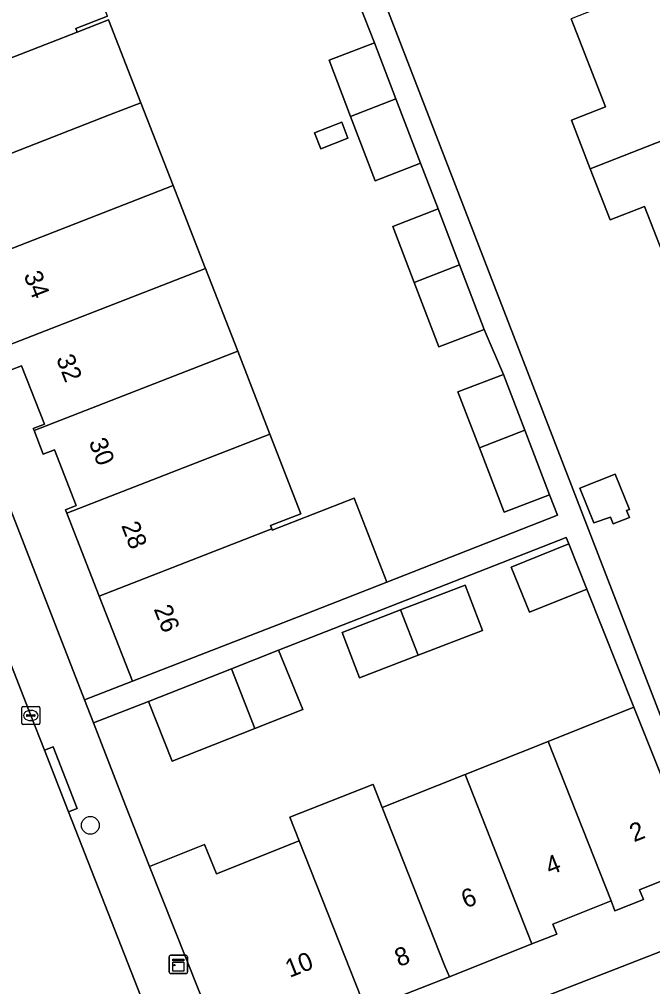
# Model space of a CAD drawing. Extents: x 159680 to 160786, y 387323 to 388340.
# Drawn here: x 160030.6 to 160065.4, y 387502 to 387555.2 of the extents above; entities that cross this region are included whole.
import ezdxf

# ---------------------------------------------------------------- set-up
doc = ezdxf.new("R2010")
doc.units = 0
for name, color, linetype in [('IMGEO_Boom', 7, 'Continuous'), ('IMGEO_Erf', 7, 'Continuous'), ('IMGEO_Kast', 7, 'Continuous'), ('IMGEO_Kolk', 7, 'Continuous'), ('IMGEO_Muur', 7, 'Continuous'), ('IMGEO_Pand', 7, 'Continuous'), ('IMGEO_Pand_nummerreeks', 7, 'Continuous'), ('IMGEO_Rijbaan_lokaal_open', 7, 'Continuous'), ('IMGEO_Voetpad_open', 7, 'Continuous')]:
    doc.layers.add(name, color=color, linetype=linetype)

msp = doc.modelspace()

# ---------------------------------------------------------------- linework, layer by layer
at = {"layer": 'IMGEO_Boom'}
msp.add_circle((160034.471, 387510.903), 0.489, dxfattribs=at)
at = {"layer": 'IMGEO_Erf'}
for points in [[(160017.573, 387560.484), (160034.159, 387517.793), (160036.787, 387518.814), (160034.961, 387523.5), (160033.187, 387528.051), (160033.114, 387528.239), (160033.694, 387528.465), (160032.5, 387531.531), (160031.883, 387531.291), (160031.378, 387532.587), (160031.336, 387532.696), (160031.95, 387532.935), (160030.698, 387536.152), (160030.129, 387535.93)], [(160049.345, 387559.465), (160066.07, 387516.165)], [(160035.42, 387555.355), (160033.674, 387554.675), (160033.751, 387554.478), (160035.473, 387555.149), (160037.246, 387550.6), (160039.018, 387546.049), (160040.742, 387541.623), (160040.791, 387541.497), (160042.564, 387536.946), (160044.336, 387532.395), (160046.041, 387528.018), (160044.368, 387527.366), (160044.436, 387527.192), (160044.463, 387527.122), (160048.965, 387528.876), (160050.764, 387524.259), (160060.128, 387527.94), (160059.689, 387529.06), (160057.192, 387528.104), (160055.839, 387531.635), (160054.659, 387534.718), (160057.156, 387535.674), (160056.106, 387538.147), (160053.609, 387537.191), (160052.256, 387540.723), (160051.076, 387543.805), (160053.573, 387544.761), (160052.609, 387547.268), (160050.112, 387546.312), (160048.759, 387549.846), (160047.579, 387552.926), (160050.076, 387553.882), (160048.979, 387556.693)], [(160066.681, 387540.361), (160064.907, 387544.897), (160063.03, 387544.163), (160061.931, 387546.973), (160060.889, 387549.637), (160062.771, 387550.371), (160060.883, 387555.206)], [(160069.127, 387505.279), (160067.819, 387508.634), (160064.637, 387507.364), (160064.847, 387506.837), (160063.284, 387506.213), (160063.071, 387506.753), (160059.873, 387505.476), (160060.091, 387504.929), (160058.727, 387504.385), (160054.2, 387502.578), (160051.005, 387501.339), (160049.647, 387500.797), (160049.355, 387501.385), (160046.255, 387500.148), (160046.314, 387500), (160046.515, 387499.498), (160045.265, 387499), (160044.991, 387499.689), (160044.698, 387499.572), (160044.527, 387500), (160044.012, 387501.289), (160041.11, 387500.131), (160041.16, 387500), (160042.036, 387497.709)], [(160045.65, 387496.123), (160055.591, 387500), (160069.127, 387505.279)]]:
    msp.add_lwpolyline(points, dxfattribs=at)
for points in [[(160046.78, 387548.948), (160048.278, 387549.533), (160048.622, 387548.651), (160047.124, 387548.067)], [(160062.128, 387527.513), (160061.361, 387529.424), (160063.3, 387530.202), (160064.081, 387528.255), (160063.926, 387528.193), (160064.076, 387527.817), (160063.19, 387527.462), (160063.041, 387527.833)], [(160064.323, 387517.392), (160061.746, 387523.871), (160058.587, 387522.604), (160057.59, 387525.092), (160060.748, 387526.358), (160060.606, 387526.72), (160044.797, 387520.524), (160046.143, 387517.271), (160043.513, 387516.23), (160038.969, 387514.433), (160037.673, 387517.703), (160034.65, 387516.529), (160036.409, 387512.001), (160037.712, 387508.645), (160040.748, 387509.857), (160041.393, 387508.239), (160045.943, 387510.055), (160045.432, 387511.354), (160049.984, 387513.146), (160049.996, 387513.15), (160050, 387513.151), (160050.502, 387511.875), (160055.062, 387513.695), (160059.623, 387515.516)], [(160049.26, 387519.008), (160048.301, 387521.504), (160051.503, 387522.735), (160055.056, 387524.099), (160056.015, 387521.603), (160052.483, 387520.246)]]:
    msp.add_lwpolyline(points, close=True, dxfattribs=at)
at = {"layer": 'IMGEO_Kast'}
for p, q in [((160038.805, 387502.837), (160038.805, 387503.678)), ((160038.805, 387503.678), (160038.805, 387502.837)), ((160038.88, 387503.762), (160039.721, 387503.762)), ((160039.721, 387503.762), (160038.88, 387503.762)), ((160039.805, 387503.687), (160039.805, 387502.846)), ((160039.805, 387502.846), (160039.805, 387503.687)), ((160039.73, 387502.762), (160038.889, 387502.762)), ((160038.889, 387502.762), (160039.73, 387502.762))]:
    msp.add_line(p, q, dxfattribs=at)
for points in [[(160039, 387503.552), (160039.6, 387503.552), (160039.6, 387503.467), (160039, 387503.467), (160039, 387503.552)], [(160039, 387503.377), (160039.6, 387503.377), (160039.6, 387502.888), (160039, 387502.888), (160039, 387503.377)]]:
    msp.add_lwpolyline(points, dxfattribs=at)
msp.add_circle((160039.084, 387503.226), 0.0377, dxfattribs=at)
for centre, start, end in [((160038.883, 387503.684), 92.4484, 184.2845), ((160038.883, 387503.684), 92.4484, 184.2845), ((160039.727, 387503.684), 2.4484, 94.2845), ((160039.727, 387503.684), 2.4484, 94.2845), ((160038.883, 387502.84), 182.4484, 274.2845), ((160038.883, 387502.84), 182.4484, 274.2845), ((160039.727, 387502.84), 272.4484, 4.2845), ((160039.727, 387502.84), 272.4484, 4.2845)]:
    msp.add_arc(centre, 0.0779, start, end, dxfattribs=at)
at = {"layer": 'IMGEO_Kolk'}
for p, q in [((160030.701, 387516.508), (160030.701, 387517.36)), ((160030.776, 387517.434), (160031.628, 387517.434)), ((160031.189, 387517.214), (160031.214, 387517.214)), ((160031.702, 387517.36), (160031.702, 387516.508)), ((160030.96, 387516.928), (160030.96, 387516.94)), ((160031.398, 387516.891), (160031, 387516.891)), ((160031.003, 387516.977), (160031.401, 387516.977)), ((160031.444, 387516.94), (160031.444, 387516.928)), ((160031.628, 387516.434), (160030.776, 387516.434)), ((160031.212, 387516.654), (160031.187, 387516.654))]:
    msp.add_line(p, q, dxfattribs=at)
for points in [[(160030.701, 387516.508), (160030.701, 387517.36)], [(160030.776, 387517.434), (160031.628, 387517.434)], [(160031.702, 387517.36), (160031.702, 387516.508)], [(160031.628, 387516.434), (160030.776, 387516.434)]]:
    msp.add_lwpolyline(points, dxfattribs=at)
for centre, radius, start, end in [((160030.778, 387517.358), 0.0765, 91.552, 178.448), ((160030.778, 387517.358), 0.0765, 91.552, 178.448), ((160031.626, 387517.358), 0.0765, 1.552, 88.448), ((160031.626, 387517.358), 0.0765, 1.552, 88.448), ((160031, 387516.937), 0.0403, 85.8775, 175.7526), ((160030.997, 387516.927), 0.0366, 178.938, 274.7102), ((160031.401, 387516.934), 0.043, 264.8664, 352.4533), ((160031.405, 387516.939), 0.0386, 1.7309, 96.639), ((160030.778, 387516.51), 0.0765, 181.552, 268.448), ((160030.778, 387516.51), 0.0765, 181.552, 268.448), ((160031.626, 387516.51), 0.0765, 271.552, 358.448), ((160031.626, 387516.51), 0.0765, 271.552, 358.448)]:
    msp.add_arc(centre, radius, start, end, dxfattribs=at)
for centre, major_axis, ratio, start_param, end_param in [((160031.188, 387516.934), (-0.387, 0.002), 0.722429, 4.712389, 7.853982), ((160031.213, 387516.934), (-0.39, 0.002), 0.717154, 1.570796, 4.712389)]:
    msp.add_ellipse(centre, major_axis=major_axis, ratio=ratio, start_param=start_param, end_param=end_param, dxfattribs=at)
at = {"layer": 'IMGEO_Muur'}
msp.add_lwpolyline([(160037.712, 387508.645), (160036.409, 387512.001)], dxfattribs=at)
at = {"layer": 'IMGEO_Pand'}
for points in [[(160018.967, 387561.012), (160020.073, 387558.169), (160021.24, 387558.623), (160024.29, 387550.792), (160033.751, 387554.478), (160033.674, 387554.675), (160035.42, 387555.355), (160033.759, 387559.622), (160032.257, 387559.036), (160032.033, 387558.948), (160031.947, 387559.17), (160029.41, 387558.183), (160026.651, 387557.11), (160024.314, 387563.098)], [(160071.415, 387559.335), (160060.883, 387555.206), (160062.771, 387550.371), (160060.889, 387549.637), (160061.931, 387546.973), (160070.476, 387550.323), (160069.537, 387552.725), (160072.948, 387555.415)], [(160037.246, 387550.6), (160035.473, 387555.149), (160033.751, 387554.478), (160024.29, 387550.792), (160024.763, 387549.577), (160025.375, 387549.816), (160026.607, 387546.653), (160026.041, 387546.432), (160026.108, 387546.259), (160035.523, 387549.928)], [(160050.076, 387553.882), (160047.579, 387552.926), (160048.759, 387549.846), (160051.25, 387550.817)], [(160050.112, 387546.312), (160052.609, 387547.268), (160051.25, 387550.817), (160048.759, 387549.846)], [(160026.108, 387546.259), (160027.881, 387541.708), (160039.018, 387546.049), (160037.246, 387550.6), (160035.523, 387549.928)], [(160070.476, 387550.323), (160061.931, 387546.973), (160063.03, 387544.163), (160064.907, 387544.897), (160066.681, 387540.361), (160077.238, 387544.5), (160075.716, 387548.393), (160071.416, 387547.919)], [(160046.78, 387548.948), (160047.124, 387548.067), (160048.622, 387548.651), (160048.278, 387549.533)], [(160040.791, 387541.497), (160040.742, 387541.623), (160039.018, 387546.049), (160027.881, 387541.708), (160028.383, 387540.418), (160028.924, 387540.629), (160030.14, 387537.506), (160029.597, 387537.295), (160029.651, 387537.157)], [(160053.573, 387544.761), (160051.076, 387543.805), (160052.256, 387540.723), (160054.748, 387541.694)], [(160053.609, 387537.191), (160056.106, 387538.147), (160054.748, 387541.694), (160052.256, 387540.723)], [(160029.651, 387537.157), (160030.129, 387535.93), (160030.698, 387536.152), (160031.95, 387532.935), (160031.336, 387532.696), (160031.378, 387532.587), (160042.564, 387536.946), (160040.791, 387541.497)], [(160031.378, 387532.587), (160031.883, 387531.291), (160032.5, 387531.531), (160033.694, 387528.465), (160033.114, 387528.239), (160033.187, 387528.051), (160044.336, 387532.395), (160042.564, 387536.946)], [(160057.156, 387535.674), (160054.659, 387534.718), (160055.839, 387531.635), (160058.331, 387532.606)], [(160044.436, 387527.192), (160044.368, 387527.366), (160046.041, 387528.018), (160044.336, 387532.395), (160033.187, 387528.051), (160034.961, 387523.5)], [(160057.192, 387528.104), (160059.689, 387529.06), (160058.331, 387532.606), (160055.839, 387531.635)], [(160062.128, 387527.513), (160063.041, 387527.833), (160063.19, 387527.462), (160064.076, 387527.817), (160063.926, 387528.193), (160064.081, 387528.255), (160063.3, 387530.202), (160061.361, 387529.424)], [(160044.436, 387527.192), (160034.961, 387523.5), (160036.787, 387518.814), (160042.015, 387520.851), (160046.261, 387522.505), (160050.764, 387524.259), (160048.965, 387528.876), (160044.463, 387527.122)], [(160060.748, 387526.358), (160057.59, 387525.092), (160058.587, 387522.604), (160061.746, 387523.871)], [(160051.503, 387522.735), (160052.483, 387520.246), (160056.015, 387521.603), (160055.056, 387524.099)], [(160052.483, 387520.246), (160051.503, 387522.735), (160048.301, 387521.504), (160049.26, 387519.008)], [(160043.513, 387516.23), (160046.143, 387517.271), (160044.797, 387520.524), (160042.224, 387519.505)], [(160042.224, 387519.505), (160037.673, 387517.703), (160038.969, 387514.433), (160043.513, 387516.23)], [(160065.965, 387513.278), (160064.323, 387517.392), (160059.623, 387515.516), (160063.071, 387506.753), (160063.284, 387506.213), (160064.847, 387506.837), (160064.637, 387507.364), (160067.819, 387508.634)], [(160059.623, 387515.516), (160055.062, 387513.695), (160058.727, 387504.385), (160060.091, 387504.929), (160059.873, 387505.476), (160063.071, 387506.753)], [(160055.062, 387513.695), (160050.502, 387511.875), (160053.932, 387503.16), (160054.2, 387502.578), (160058.727, 387504.385)], [(160050.502, 387511.875), (160050, 387513.151), (160049.996, 387513.15), (160049.984, 387513.146), (160045.432, 387511.354), (160045.943, 387510.055), (160049.355, 387501.385), (160049.647, 387500.797), (160051.005, 387501.339), (160054.2, 387502.578), (160053.932, 387503.16)], [(160041.11, 387500.131), (160044.012, 387501.289), (160044.527, 387500), (160044.698, 387499.572), (160044.991, 387499.689), (160045.265, 387499), (160046.515, 387499.498), (160046.314, 387500), (160046.255, 387500.148), (160049.355, 387501.385), (160045.943, 387510.055), (160041.393, 387508.239), (160040.748, 387509.857), (160037.712, 387508.645)]]:
    msp.add_lwpolyline(points, close=True, dxfattribs=at)
at = {"layer": 'IMGEO_Rijbaan_lokaal_open'}
msp.add_lwpolyline([(160046.513, 387477.713), (160045.765, 387479.734), (160039.549, 387495.628), (160039.516, 387495.711), (160039.429, 387495.946), (160033.273, 387511.651), (160031.95, 387515.027), (160031.202, 387516.934), (160024.093, 387535.131), (160021.109, 387542.72), (160014.836, 387540.165), (160017.868, 387532.491), (160033.182, 387493.23), (160040.063, 387475.562), (160047.543, 387456.377), (160054.279, 387439.075), (160061.763, 387419.918), (160069.174, 387400.967), (160069.426, 387400.286), (160069.653, 387399.763)], dxfattribs=at)
at = {"layer": 'IMGEO_Voetpad_open'}
for points in [[(159987.067, 387629.663), (159987.361, 387628.927), (159995.615, 387607.919), (159999.072, 387599.055), (160000.343, 387595.839), (160003.105, 387588.75), (160008.272, 387575.517), (160010.227, 387570.53), (160017.67, 387551.468), (160019.899, 387545.798), (160021.109, 387542.72), (160024.093, 387535.131), (160031.202, 387516.934), (160031.95, 387515.027), (160032.421, 387515.214), (160033.739, 387511.836), (160033.273, 387511.651), (160039.429, 387495.946), (160039.516, 387495.711), (160039.549, 387495.628)], [(160043.911, 387491.803), (160042.036, 387497.709), (160041.16, 387500), (160041.11, 387500.131), (160037.712, 387508.645), (160036.409, 387512.001), (160034.65, 387516.529), (160034.159, 387517.793), (160017.573, 387560.484), (160014.618, 387568.087)], [(160066.07, 387516.165), (160049.345, 387559.465)], [(160048.979, 387556.693), (160050.076, 387553.882), (160051.25, 387550.817), (160052.609, 387547.268), (160053.573, 387544.761), (160054.748, 387541.694), (160056.106, 387538.147), (160057.156, 387535.674), (160058.331, 387532.606), (160059.689, 387529.06), (160060.128, 387527.94), (160050.764, 387524.259), (160046.261, 387522.505), (160042.015, 387520.851), (160036.787, 387518.814), (160034.159, 387517.793), (160034.65, 387516.529), (160037.673, 387517.703), (160042.224, 387519.505), (160044.797, 387520.524), (160060.606, 387526.72), (160060.748, 387526.358), (160061.746, 387523.871), (160064.323, 387517.392), (160065.965, 387513.278)], [(160090.391, 387513.528), (160089.429, 387513.205), (160082.66, 387510.557), (160070.164, 387505.683), (160069.127, 387505.279), (160055.591, 387500), (160045.65, 387496.123)]]:
    msp.add_lwpolyline(points, dxfattribs=at)
msp.add_lwpolyline([(160032.421, 387515.214), (160031.95, 387515.027), (160033.273, 387511.651), (160033.739, 387511.836)], close=True, dxfattribs=at)

# ---------------------------------------------------------------- texts
at = {"layer": 'IMGEO_Pand_nummerreeks'}
for s, rotation, p in [('34', 291.2913, (160030.795, 387541.131)), ('32', 291.2913, (160032.58, 387536.549)), ('30', 291.2913, (160034.369, 387531.958)), ('28', 291.2913, (160036.156, 387527.373)), ('26', 291.2909, (160037.942, 387522.791)), ('2', 21.4974, (160064.327, 387509.967)), ('4', 21.4974, (160059.708, 387508.148)), ('6', 21.4992, (160055.086, 387506.328)), ('10', 21.4992, (160045.419, 387502.519)), ('8', 20.9989, (160051.421, 387503.111))]:
    msp.add_text(s, height=1, rotation=rotation, dxfattribs=at).set_placement(p)

doc.saveas('drawing.dxf')
